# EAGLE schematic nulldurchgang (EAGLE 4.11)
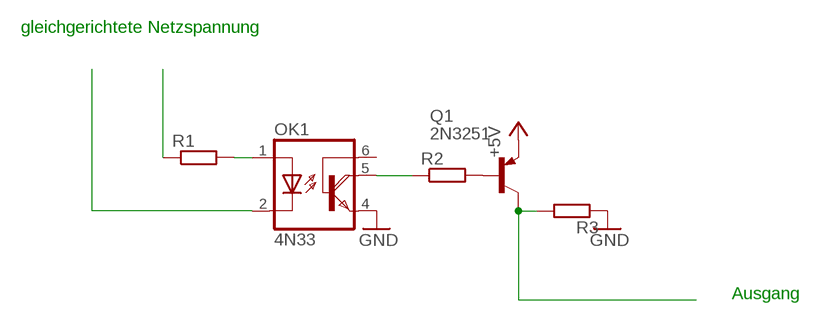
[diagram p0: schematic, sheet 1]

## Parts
OK1  4N33  [DIL06]
Q1  2N3251  [TO18]
R1  R-EU_0204/2V  [0204V]
R2  R-EU_0204/2V  [0204V]
R3  R-EU_0204/2V  [0204V]

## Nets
+5V: Q1.1(E)
GND: OK1.4(E) R3.1
N$1: Q1.2(B) R2.2
N$2: OK1.5(COL) R2.1
N$3: Q1.3(C) R3.2
N$4: OK1.1(A) R1.2
N$5: OK1.2(C)
N$6: R1.1
Unconnected: OK1.6(B)

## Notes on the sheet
- gleichgerichtete Netzspannung
- Ausgang

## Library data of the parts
OK1 = optocoupler:4N33: MOTOROLA OPTO COUPLER
Q1 = transistor-pnp:2N3251: PNP Transistror
R1-R3 = rcl:R-EU_: RESISTOR, European symbol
